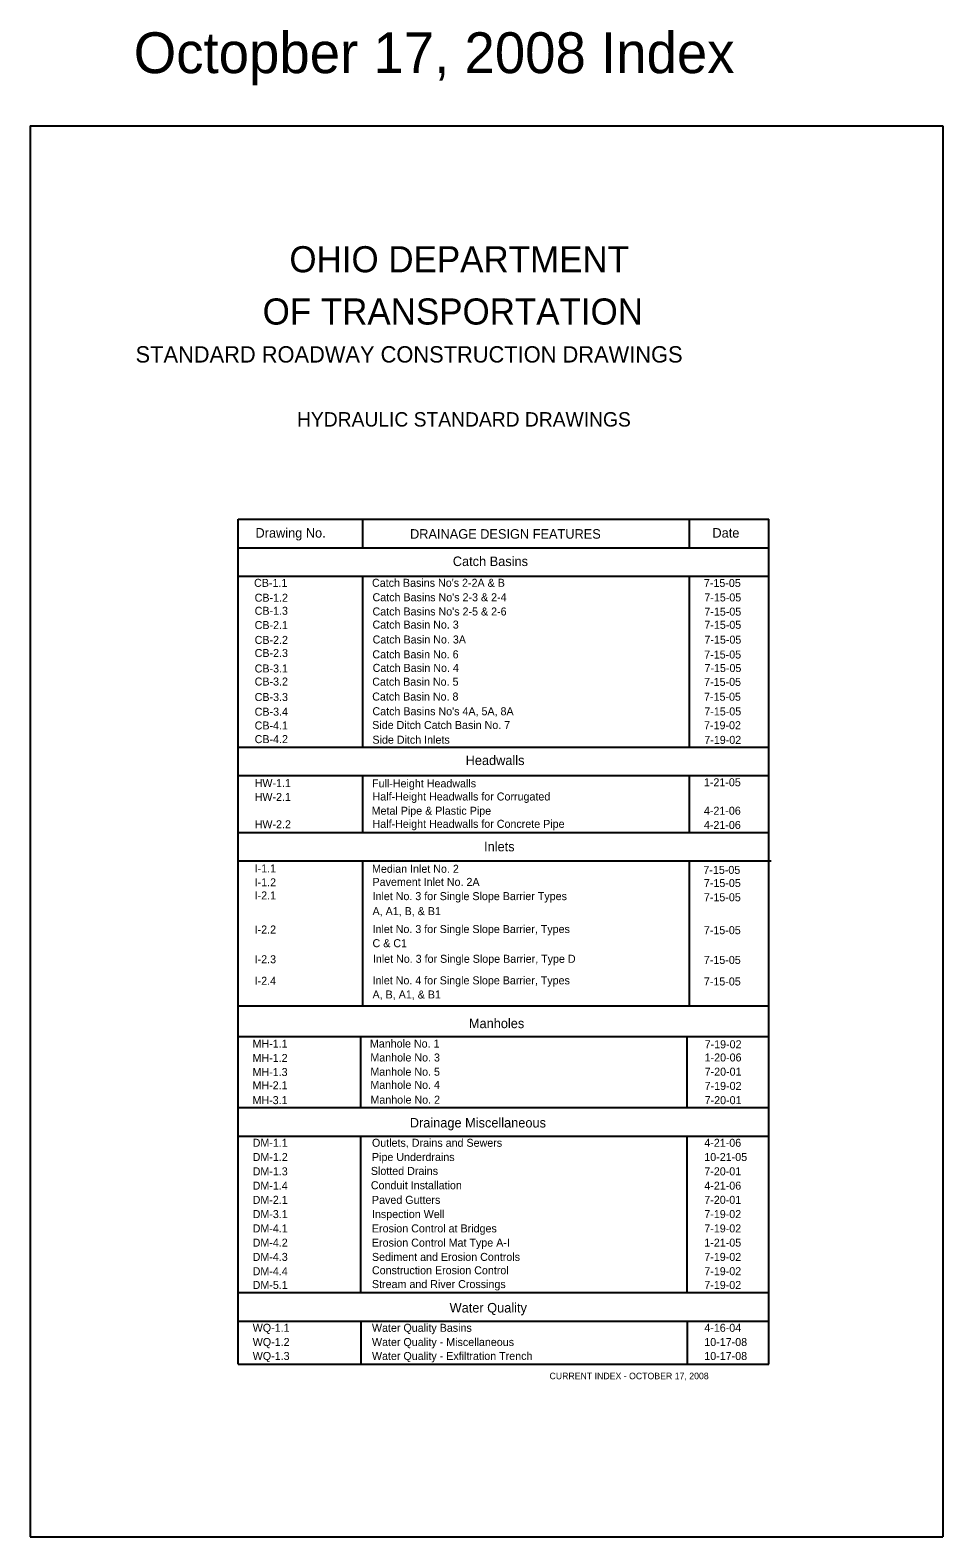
# Model space of a CAD drawing. Extents: x 146 to 619, y 56 to 2134.
# Drawn here: x 597.17 to 619.17, y 2097.9 to 2134.21 of the extents above; entities that cross this region are included whole.
import ezdxf

# ---------------------------------------------------------------- set-up
doc = ezdxf.new("R2010")
doc.units = 0
doc.layers.add('Level 1', color=7, linetype='Continuous')

msp = doc.modelspace()

# ---------------------------------------------------------------- linework, layer by layer
at = {"layer": 'Level 1'}
for p, q in [((597.168, 2131.9), (619.168, 2131.9)), ((597.168, 2131.9), (597.168, 2097.9)), ((619.168, 2131.9), (619.168, 2097.9)), ((602.185, 2102.061), (602.185, 2122.419)), ((602.185, 2122.419), (614.974, 2122.419)), ((602.185, 2122.419), (602.185, 2122.419)), ((605.188, 2121.733), (605.188, 2122.419)), ((613.058, 2121.733), (613.058, 2122.419)), ((614.974, 2102.061), (614.974, 2122.419)), ((614.974, 2122.419), (614.974, 2122.419)), ((602.185, 2121.733), (614.974, 2121.733)), ((602.185, 2121.047), (614.974, 2121.047)), ((605.188, 2116.932), (605.188, 2121.047)), ((613.058, 2116.932), (613.058, 2121.047)), ((602.185, 2116.932), (614.974, 2116.932)), ((602.185, 2116.246), (614.974, 2116.246)), ((605.188, 2114.872), (605.188, 2116.246)), ((613.058, 2114.872), (613.058, 2116.246)), ((602.185, 2114.874), (614.974, 2114.874)), ((602.185, 2114.188), (614.974, 2114.188)), ((602.237, 2114.188), (615.026, 2114.188)), ((605.188, 2114.188), (605.188, 2114.192)), ((605.188, 2110.695), (605.188, 2114.188)), ((613.058, 2114.188), (613.058, 2114.189)), ((613.058, 2110.695), (613.058, 2114.188)), ((602.185, 2110.695), (614.974, 2110.695)), ((602.185, 2109.958), (614.974, 2109.958)), ((605.137, 2108.243), (605.137, 2109.958)), ((613.007, 2108.266), (613.007, 2109.958)), ((605.137, 2108.243), (605.137, 2109.272)), ((613.007, 2108.243), (613.007, 2109.272)), ((602.185, 2108.243), (614.974, 2108.243)), ((602.185, 2107.557), (614.974, 2107.557)), ((605.137, 2106.185), (605.137, 2107.557)), ((613.007, 2106.185), (613.007, 2107.557)), ((613.007, 2104.826), (613.007, 2107.536)), ((605.137, 2104.283), (605.137, 2107.027)), ((605.137, 2103.785), (605.137, 2105.156)), ((613.007, 2103.784), (613.007, 2105.177)), ((602.185, 2103.785), (614.974, 2103.785)), ((602.185, 2103.099), (614.974, 2103.099)), ((605.137, 2103.099), (605.137, 2102.061)), ((613.007, 2103.098), (613.007, 2102.062)), ((602.185, 2102.061), (614.974, 2102.061)), ((597.168, 2097.9), (619.168, 2097.9))]:
    msp.add_line(p, q, dxfattribs=at)

# ---------------------------------------------------------------- texts
for s, height, p in [('Octopber 17, 2008 Index', 0.98375, (599.666, 2133.169)), ('OHIO DEPARTMENT', 0.6296, (603.417, 2128.37)), ('OF TRANSPORTATION', 0.6296, (602.772, 2127.111)), ('STANDARD ROADWAY CONSTRUCTION DRAWINGS', 0.3935, (599.71, 2126.196)), ('HYDRAULIC STANDARD DRAWINGS', 0.34707, (603.601, 2124.653)), ('Drawing No.', 0.23, (602.6, 2121.977)), ('DRAINAGE DESIGN FEATURES', 0.23, (606.325, 2121.951)), ('Date', 0.23, (613.614, 2121.977)), ('Catch Basins', 0.23, (607.356, 2121.292)), ('CB-1.1', 0.1928, (602.566, 2120.791)), ("Catch Basins No's 2-2A & B", 0.1928, (605.409, 2120.792)), ('7-15-05', 0.1928, (613.408, 2120.788)), ('CB-1.2', 0.1928, (602.58, 2120.433)), ("Catch Basins No's 2-3 & 2-4", 0.1928, (605.421, 2120.444)), ('7-15-05', 0.1928, (613.419, 2120.44)), ('CB-1.3', 0.1928, (602.58, 2120.118)), ("Catch Basins No's 2-5 & 2-6", 0.1928, (605.421, 2120.101)), ('7-15-05', 0.1928, (613.419, 2120.097)), ('CB-2.1', 0.1928, (602.58, 2119.774)), ('Catch Basin No. 3', 0.1928, (605.421, 2119.785)), ('7-15-05', 0.1928, (613.419, 2119.78)), ('CB-2.2', 0.1928, (602.58, 2119.416)), ('Catch Basin No. 3A', 0.1928, (605.423, 2119.426)), ('7-15-05', 0.1928, (613.421, 2119.422)), ('CB-2.3', 0.1928, (602.58, 2119.1)), ('Catch Basin No. 6', 0.1928, (605.418, 2119.068)), ('7-15-05', 0.1928, (613.416, 2119.064)), ('CB-3.1', 0.1928, (602.58, 2118.728)), ('Catch Basin No. 4', 0.1928, (605.424, 2118.742)), ('7-15-05', 0.1928, (613.422, 2118.738)), ('CB-3.2', 0.1928, (602.58, 2118.413)), ('Catch Basin No. 5', 0.1928, (605.415, 2118.409)), ('7-15-05', 0.1928, (613.414, 2118.405)), ('CB-3.3', 0.1928, (602.58, 2118.04)), ('Catch Basin No. 8', 0.1928, (605.414, 2118.051)), ('7-15-05', 0.1928, (613.412, 2118.047)), ('CB-3.4', 0.1928, (602.58, 2117.686)), ("Catch Basins No's 4A, 5A, 8A", 0.1928, (605.419, 2117.697)), ('7-15-05', 0.1928, (613.418, 2117.693)), ('CB-4.1', 0.1928, (602.58, 2117.354)), ('Side Ditch Catch Basin No. 7', 0.1928, (605.414, 2117.366)), ('7-19-02', 0.1928, (613.412, 2117.361)), ('CB-4.2', 0.1928, (602.58, 2117.025)), ('Side Ditch Inlets', 0.1928, (605.419, 2117.011)), ('7-19-02', 0.1928, (613.418, 2117.007)), ('Headwalls', 0.23, (607.665, 2116.497)), ('HW-1.1', 0.1928, (602.58, 2115.967)), ('Full-Height Headwalls', 0.1928, (605.409, 2115.959)), ('1-21-05', 0.1928, (613.408, 2115.986)), ('HW-2.1', 0.1928, (602.58, 2115.632)), ('Half-Height Headwalls for Corrugated ', 0.1928, (605.421, 2115.643)), ('       Metal Pipe & Plastic Pipe', 0.1928, (604.898, 2115.3)), ('Half-Height Headwalls for Concrete Pipe', 0.1928, (605.421, 2114.984)), ('4-21-06', 0.1928, (613.408, 2115.3)), ('HW-2.2', 0.1928, (602.58, 2114.974)), ('4-21-06', 0.1928, (613.408, 2114.957)), ('Inlets', 0.23, (608.11, 2114.418)), ('I-1.1', 0.1928, (602.58, 2113.91)), ('Median Inlet No. 2', 0.1928, (605.409, 2113.901)), ('I-1.2', 0.1928, (602.58, 2113.574)), ('Pavement Inlet No. 2A', 0.1928, (605.421, 2113.585)), ('7-15-05', 0.1928, (613.396, 2113.874)), ('7-15-05', 0.1928, (613.408, 2113.558)), ('I-2.1', 0.1928, (602.58, 2113.259)), ('Inlet No. 3 for Single Slope Barrier Types ', 0.1928, (605.421, 2113.242)), ('7-15-05', 0.1928, (613.408, 2113.215)), ('A, A1, B, & B1', 0.1928, (605.421, 2112.881)), ('I-2.2', 0.1928, (602.58, 2112.438)), ('Inlet No. 3 for Single Slope Barrier, Types', 0.1928, (605.421, 2112.449)), ('C & C1', 0.1928, (605.421, 2112.108)), ('7-15-05', 0.1928, (613.407, 2112.422)), ('I-2.3', 0.1928, (602.58, 2111.721)), ('Inlet No. 3 for Single Slope Barrier, Type D', 0.1928, (605.429, 2111.732)), ('7-15-05', 0.1928, (613.407, 2111.705)), ('I-2.4', 0.1928, (602.58, 2111.202)), ('Inlet No. 4 for Single Slope Barrier, Types', 0.1928, (605.421, 2111.213)), ('7-15-05', 0.1928, (613.407, 2111.186)), ('A, B, A1, & B1', 0.1928, (605.421, 2110.872)), ('Manholes', 0.23, (607.744, 2110.158)), ('MH-1.1', 0.1928, (602.528, 2109.687)), ('Manhole No. 1', 0.1928, (605.358, 2109.69)), ('7-19-02', 0.1928, (613.426, 2109.672)), ('MH-1.2', 0.1928, (602.528, 2109.343)), ('Manhole No. 3', 0.1928, (605.369, 2109.354)), ('1-20-06', 0.1928, (613.426, 2109.355)), ('MH-1.3', 0.1928, (602.528, 2109.003)), ('Manhole No. 5', 0.1928, (605.369, 2109.011)), ('7-20-01', 0.1928, (613.426, 2109.012)), ('MH-2.1', 0.1928, (602.528, 2108.684)), ('Manhole No. 4', 0.1928, (605.369, 2108.695)), ('7-19-02', 0.1928, (613.426, 2108.669)), ('MH-3.1', 0.1928, (602.528, 2108.326)), ('Manhole No. 2', 0.1928, (605.371, 2108.337)), ('7-20-01', 0.1928, (613.426, 2108.326)), ('Drainage Miscellaneous', 0.23, (606.319, 2107.764)), ('DM-1.1', 0.1928, (602.532, 2107.299)), ('Outlets, Drains and Sewers', 0.1928, (605.407, 2107.299)), ('4-21-06', 0.1928, (613.418, 2107.299)), ('DM-1.2', 0.1928, (602.532, 2106.956)), ('Slotted Drains', 0.1928, (605.381, 2106.621)), ('Pipe Underdrains', 0.1928, (605.407, 2106.956)), ('10-21-05', 0.1928, (613.418, 2106.956)), ('DM-1.3', 0.1928, (602.532, 2106.611)), ('DM-1.4', 0.1928, (602.532, 2106.266)), ('Conduit Installation', 0.1928, (605.381, 2106.276)), ('4-21-06', 0.1928, (613.418, 2106.266)), ('7-20-01', 0.1928, (613.418, 2106.611)), ('DM-2.1', 0.1928, (602.532, 2105.924)), ('Paved Gutters', 0.1928, (605.407, 2105.924)), ('7-20-01', 0.1928, (613.418, 2105.924)), ('DM-3.1', 0.1928, (602.532, 2105.581)), ('Inspection Well', 0.1928, (605.407, 2105.581)), ('7-19-02', 0.1928, (613.418, 2105.581)), ('DM-4.1', 0.1928, (602.532, 2105.236)), ('Erosion Control at Bridges', 0.1928, (605.407, 2105.236)), ('7-19-02', 0.1928, (613.418, 2105.236)), ('DM-4.2', 0.1928, (602.532, 2104.893)), ('Erosion Control Mat Type A-I', 0.1928, (605.407, 2104.893)), ('1-21-05', 0.1928, (613.418, 2104.893)), ('DM-4.3', 0.1928, (602.532, 2104.549)), ('Sediment and Erosion Controls', 0.1928, (605.407, 2104.549)), ('7-19-02', 0.1928, (613.418, 2104.549)), ('DM-4.4', 0.1928, (602.532, 2104.204)), ('Construction Erosion Control', 0.1928, (605.407, 2104.227)), ('7-19-02', 0.1928, (613.418, 2104.204)), ('DM-5.1', 0.1928, (602.532, 2103.873)), ('Stream and River Crossings', 0.1928, (605.407, 2103.894)), ('7-19-02', 0.1928, (613.418, 2103.873)), ('Water Quality', 0.23, (607.279, 2103.306)), ('WQ-1.1', 0.1928, (602.533, 2102.841)), ('Water Quality Basins', 0.1928, (605.407, 2102.841)), ('4-16-04', 0.1928, (613.418, 2102.841)), ('WQ-1.2', 0.1928, (602.533, 2102.498)), ('Water Quality - Miscellaneous', 0.1928, (605.407, 2102.498)), ('10-17-08', 0.1928, (613.418, 2102.498)), ('WQ-1.3', 0.1928, (602.533, 2102.162)), ('Water Quality - Exfiltration Trench', 0.1928, (605.407, 2102.162)), ('10-17-08', 0.1928, (613.418, 2102.162)), ('CURRENT INDEX - OCTOBER 17, 2008', 0.1574, (609.687, 2101.698))]:
    msp.add_text(s, height=height, dxfattribs=at).set_placement(p)

doc.saveas('drawing.dxf')
